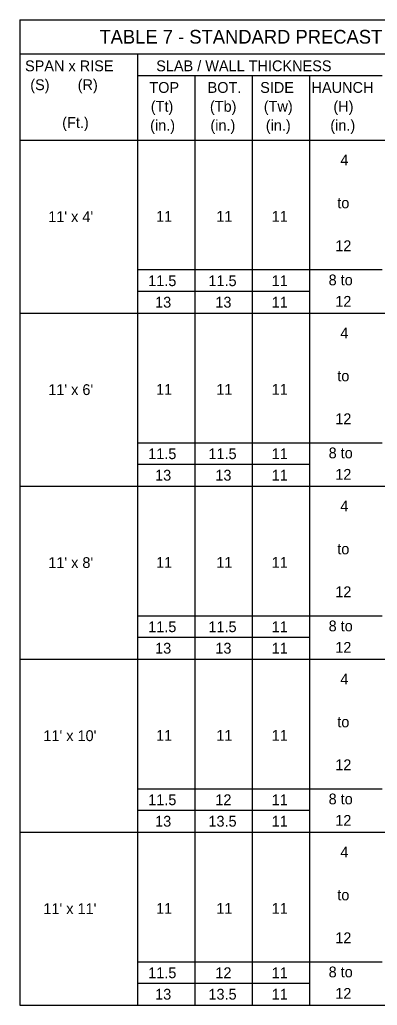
# Model space of a CAD drawing. Extents: x 10351.18 to 10353.4, y 76399.49 to 76400.59.
# Drawn here: x 10351.192 to 10351.4, y 76399.925 to 76400.5 of the extents above; entities that cross this region are included whole.
import ezdxf

# ---------------------------------------------------------------- set-up
doc = ezdxf.new("R2010")
doc.units = 0
doc.layers.add('AdhocPoint_dp', color=7, linetype='Continuous')
doc.layers.add('PlotBorder_dp', color=7, linetype='Continuous')

msp = doc.modelspace()

# ---------------------------------------------------------------- linework, layer by layer
at = {"layer": 'PlotBorder_dp'}
for p, q in [((10351.19191, 76400.49971), (10351.19191, 76399.92549)), ((10351.19191, 76400.49971), (10351.78665, 76400.49971)), ((10351.19191, 76400.47984), (10351.78665, 76400.47984)), ((10351.26055, 76400.47984), (10351.26055, 76399.92549)), ((10351.26055, 76400.46724), (10351.40299, 76400.46724)), ((10351.29391, 76400.46724), (10351.29391, 76399.92549)), ((10351.32727, 76400.46724), (10351.32727, 76399.92549)), ((10351.36063, 76400.46724), (10351.36063, 76399.92549)), ((10351.19191, 76400.42949), (10351.78665, 76400.42949)), ((10351.40299, 76400.35389), (10351.26055, 76400.35389)), ((10351.36063, 76400.34129), (10351.26055, 76400.34129)), ((10351.19191, 76400.32869), (10351.70926, 76400.32869)), ((10351.40299, 76400.25309), (10351.26055, 76400.25309)), ((10351.36063, 76400.24049), (10351.26055, 76400.24049)), ((10351.19191, 76400.22789), (10351.70926, 76400.22789)), ((10351.40299, 76400.15229), (10351.26055, 76400.15229)), ((10351.36063, 76400.13969), (10351.26055, 76400.13969)), ((10351.19191, 76400.12709), (10351.70926, 76400.12709)), ((10351.40299, 76400.05149), (10351.26055, 76400.05149)), ((10351.36063, 76400.03889), (10351.26055, 76400.03889)), ((10351.19191, 76400.02629), (10351.70926, 76400.02629)), ((10351.40299, 76399.95069), (10351.26055, 76399.95069)), ((10351.36063, 76399.93809), (10351.26055, 76399.93809)), ((10351.19191, 76399.92549), (10351.78665, 76399.92549))]:
    msp.add_line(p, q, dxfattribs=at)

# ---------------------------------------------------------------- texts
at = {"layer": 'AdhocPoint_dp'}
for s, height, p in [('TABLE 7 - STANDARD PRECAST BOX CULVERT DESIGNS (2" COVER) - 11\' SPANS', 0.008, (10351.23831, 76400.48578)), ('SLAB / WALL THICKNESS', 0.0063, (10351.27137, 76400.46968)), ("11' x 4'", 0.0063, (10351.2085, 76400.38182))]:
    msp.add_text(s, height=height, dxfattribs=at).set_placement(p)
at = {"layer": 'PlotBorder_dp'}
for s, p in [('SPAN x RISE', (10351.195, 76400.46968)), ('(S)       (R)', (10351.19804, 76400.45868)), ('TOP', (10351.26737, 76400.45708)), ('BOT.', (10351.3013, 76400.45708)), ('SIDE', (10351.3319, 76400.45708)), ('HAUNCH', (10351.36179, 76400.45708)), ('(Tt)', (10351.26822, 76400.44608)), ('(Tb)', (10351.30264, 76400.44608)), ('(Tw)', (10351.334, 76400.44608)), ('(H)', (10351.37453, 76400.44608)), ('(Ft.)', (10351.21662, 76400.43668)), ('(in.)', (10351.26783, 76400.43508)), ('(in.)', (10351.30292, 76400.43508)), ('(in.)', (10351.33516, 76400.43508)), ('(in.)', (10351.37272, 76400.43508)), ('4', (10351.37857, 76400.41485)), ('to', (10351.37679, 76400.38985)), ('11', (10351.27131, 76400.38198)), ('11', (10351.30638, 76400.38198)), ('11', (10351.33862, 76400.38198)), ('12', (10351.37562, 76400.36485)), ('11.5', (10351.2667, 76400.34448)), ('11.5', (10351.30177, 76400.34448)), ('11', (10351.33862, 76400.34448)), ('8 to', (10351.37175, 76400.34496)), ('13', (10351.27074, 76400.33198)), ('13', (10351.30581, 76400.33198)), ('11', (10351.33862, 76400.33198)), ('12', (10351.37562, 76400.33246)), ('4', (10351.37857, 76400.31405)), ('to', (10351.37679, 76400.28905)), ("11' x 6'", (10351.20852, 76400.28104)), ('11', (10351.27131, 76400.28118)), ('11', (10351.30638, 76400.28118)), ('11', (10351.33862, 76400.28118)), ('12', (10351.37562, 76400.26405)), ('11.5', (10351.2667, 76400.24368)), ('11.5', (10351.30177, 76400.24368)), ('11', (10351.33862, 76400.24368)), ('8 to', (10351.37175, 76400.24416)), ('13', (10351.27074, 76400.23118)), ('13', (10351.30581, 76400.23118)), ('11', (10351.33862, 76400.23118)), ('12', (10351.37562, 76400.23166)), ('4', (10351.37857, 76400.21325)), ('to', (10351.37679, 76400.18825)), ("11' x 8'", (10351.20852, 76400.18026)), ('11', (10351.27131, 76400.18038)), ('11', (10351.30638, 76400.18038)), ('11', (10351.33862, 76400.18038)), ('12', (10351.37562, 76400.16325)), ('8 to', (10351.37175, 76400.14336)), ('11.5', (10351.2667, 76400.14288)), ('11.5', (10351.30177, 76400.14288)), ('11', (10351.33862, 76400.14288)), ('13', (10351.27074, 76400.13038)), ('13', (10351.30581, 76400.13038)), ('11', (10351.33862, 76400.13038)), ('12', (10351.37562, 76400.13086)), ('4', (10351.37857, 76400.11245)), ('to', (10351.37679, 76400.08745)), ("11' x 10'", (10351.20569, 76400.07942)), ('11', (10351.27131, 76400.07958)), ('11', (10351.30638, 76400.07958)), ('11', (10351.33862, 76400.07958)), ('12', (10351.37562, 76400.06245)), ('11.5', (10351.2667, 76400.04208)), ('12', (10351.30581, 76400.04208)), ('11', (10351.33862, 76400.04208)), ('8 to', (10351.37175, 76400.04256)), ('13', (10351.27074, 76400.02958)), ('13.5', (10351.30177, 76400.02958)), ('11', (10351.33862, 76400.02958)), ('12', (10351.37562, 76400.03006)), ('4', (10351.37857, 76400.01165)), ('to', (10351.37679, 76399.98665)), ("11' x 11'", (10351.20569, 76399.97864)), ('11', (10351.27131, 76399.97878)), ('11', (10351.30638, 76399.97878)), ('11', (10351.33862, 76399.97878)), ('12', (10351.37562, 76399.96165)), ('11.5', (10351.2667, 76399.94128)), ('12', (10351.30581, 76399.94128)), ('11', (10351.33862, 76399.94128)), ('8 to', (10351.37175, 76399.94176)), ('13', (10351.27074, 76399.92878)), ('13.5', (10351.30177, 76399.92878)), ('11', (10351.33862, 76399.92878)), ('12', (10351.37562, 76399.92926))]:
    msp.add_text(s, height=0.0063, dxfattribs=at).set_placement(p)

doc.saveas('drawing.dxf')
